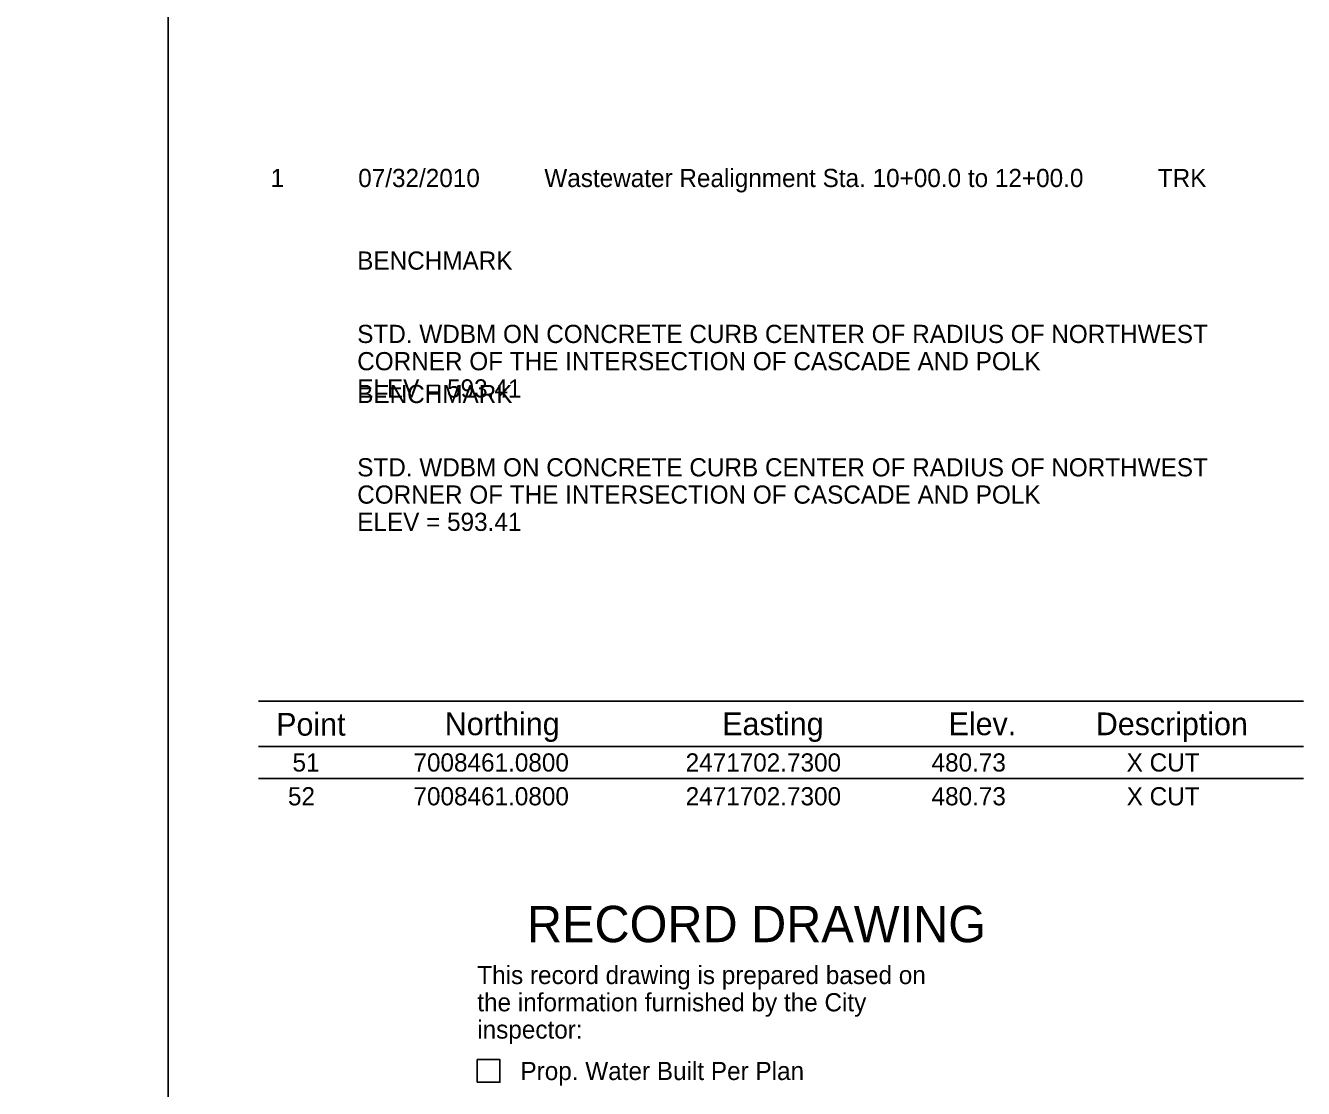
# Model space of a CAD drawing. Extents: x -4115 to -3256, y -1337 to -847.
# Drawn here: x -3411.1 to -3270.5, y -1212.2 to -1095.2 of the extents above; entities that cross this region are included whole.
import ezdxf

# ---------------------------------------------------------------- set-up
doc = ezdxf.new("R2010")
doc.units = 0
for name, color, linetype in [('G_BORDER', 7, 'Continuous'), ('G_SHEET_EDGE', 7, 'Continuous'), ('G_SIGNATURE BLOCK', 7, 'Continuous')]:
    doc.layers.add(name, color=color, linetype=linetype)

msp = doc.modelspace()

# ---------------------------------------------------------------- linework, layer by layer
at = {"layer": 'G_BORDER'}
for p, q in [((-3385.52, -1169.53), (-3270.52, -1169.53)), ((-3385.52, -1174.53), (-3270.52, -1174.53)), ((-3385.52, -1178.03), (-3270.52, -1178.03))]:
    msp.add_line(p, q, dxfattribs=at)
at = {"layer": 'G_SHEET_EDGE'}
msp.add_lwpolyline([(-4115.45, -1331.8), (-3395.45, -1331.8), (-3395.45, -851.8), (-4115.45, -851.8)], close=True, dxfattribs=at)
at = {"layer": 'G_SIGNATURE BLOCK'}
msp.add_lwpolyline([(-3361.43, -1211.48), (-3358.93, -1211.48), (-3358.93, -1208.98), (-3361.43, -1208.98)], close=True, dxfattribs=at)

# ---------------------------------------------------------------- texts
at = {"layer": 'G_BORDER'}
for s, height, p in [('07/32/2010', 2, (-3374.53, -1112.96)), ('Wastewater Realignment Sta. 10+00.0 to 12+00.0', 2, (-3354.05, -1112.96)), ('1', 2, (-3384.17, -1112.96)), ('TRK', 2, (-3286.54, -1112.96)), ('BENCHMARK', 2, (-3374.64, -1122.05)), ('STD. WDBM ON CONCRETE CURB CENTER OF RADIUS OF NORTHWEST', 2, (-3374.64, -1130.12)), ('CORNER OF THE INTERSECTION OF CASCADE AND POLK', 2, (-3374.64, -1133.12)), ('ELEV = 593.41', 2, (-3374.64, -1136.12)), ('BENCHMARK', 2, (-3374.64, -1136.73)), ('STD. WDBM ON CONCRETE CURB CENTER OF RADIUS OF NORTHWEST', 2, (-3374.64, -1144.8)), ('CORNER OF THE INTERSECTION OF CASCADE AND POLK', 2, (-3374.64, -1147.8)), ('ELEV = 593.41', 2, (-3374.64, -1150.8)), ('Point', 2.5, (-3383.55, -1173.33)), ('Northing', 2.5, (-3365, -1173.28)), ('Easting', 2.5, (-3334.47, -1173.28)), ('Elev.', 2.5, (-3309.56, -1173.28)), ('Description', 2.5, (-3293.36, -1173.28)), ('51', 2, (-3381.76, -1177.28)), ('7008461.0800', 2, (-3368.45, -1177.28)), ('2471702.7300', 2, (-3338.5, -1177.28)), ('480.73', 2, (-3311.44, -1177.28)), ('X CUT', 2, (-3289.97, -1177.28)), ('52', 2, (-3382.26, -1181)), ('7008461.0800', 2, (-3368.45, -1181)), ('2471702.7300', 2, (-3338.5, -1181)), ('480.73', 2, (-3311.44, -1181)), ('X CUT', 2, (-3289.97, -1181))]:
    msp.add_text(s, height=height, dxfattribs=at).set_placement(p)
at = {"layer": 'G_SIGNATURE BLOCK'}
msp.add_text('RECORD DRAWING', height=4, rotation=360, dxfattribs=at).set_placement((-3355.96, -1196.06))
for s, p in [('This record drawing is prepared based on', (-3361.43, -1200.67)), ('the information furnished by the City', (-3361.43, -1203.67)), ('inspector:', (-3361.43, -1206.67)), ('Prop. Water Built Per Plan', (-3356.68, -1211.23))]:
    msp.add_text(s, height=2, dxfattribs=at).set_placement(p)

doc.saveas('drawing.dxf')
